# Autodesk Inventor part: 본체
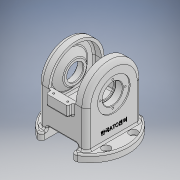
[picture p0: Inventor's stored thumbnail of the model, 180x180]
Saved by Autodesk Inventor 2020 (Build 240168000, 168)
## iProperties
Created: 2025-02
Part Number: 본체
Material: 알루미늄 6061
Document SubType Name: Modeling
Designer: 1강의실14
Density: 2.7 g/cm^3
Appearance: 알루미늄 - 평지
Mass: 1199.24 g
Surface Area: 1051.82 cm^2
Volume: 444.164 cm^3
Sending System: Autodesk Inventor 2025
Preprocessor: ST-DEVELOPER v20
Author: jhkim
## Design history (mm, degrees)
feature "솔리드2"
node "솔리드1"
